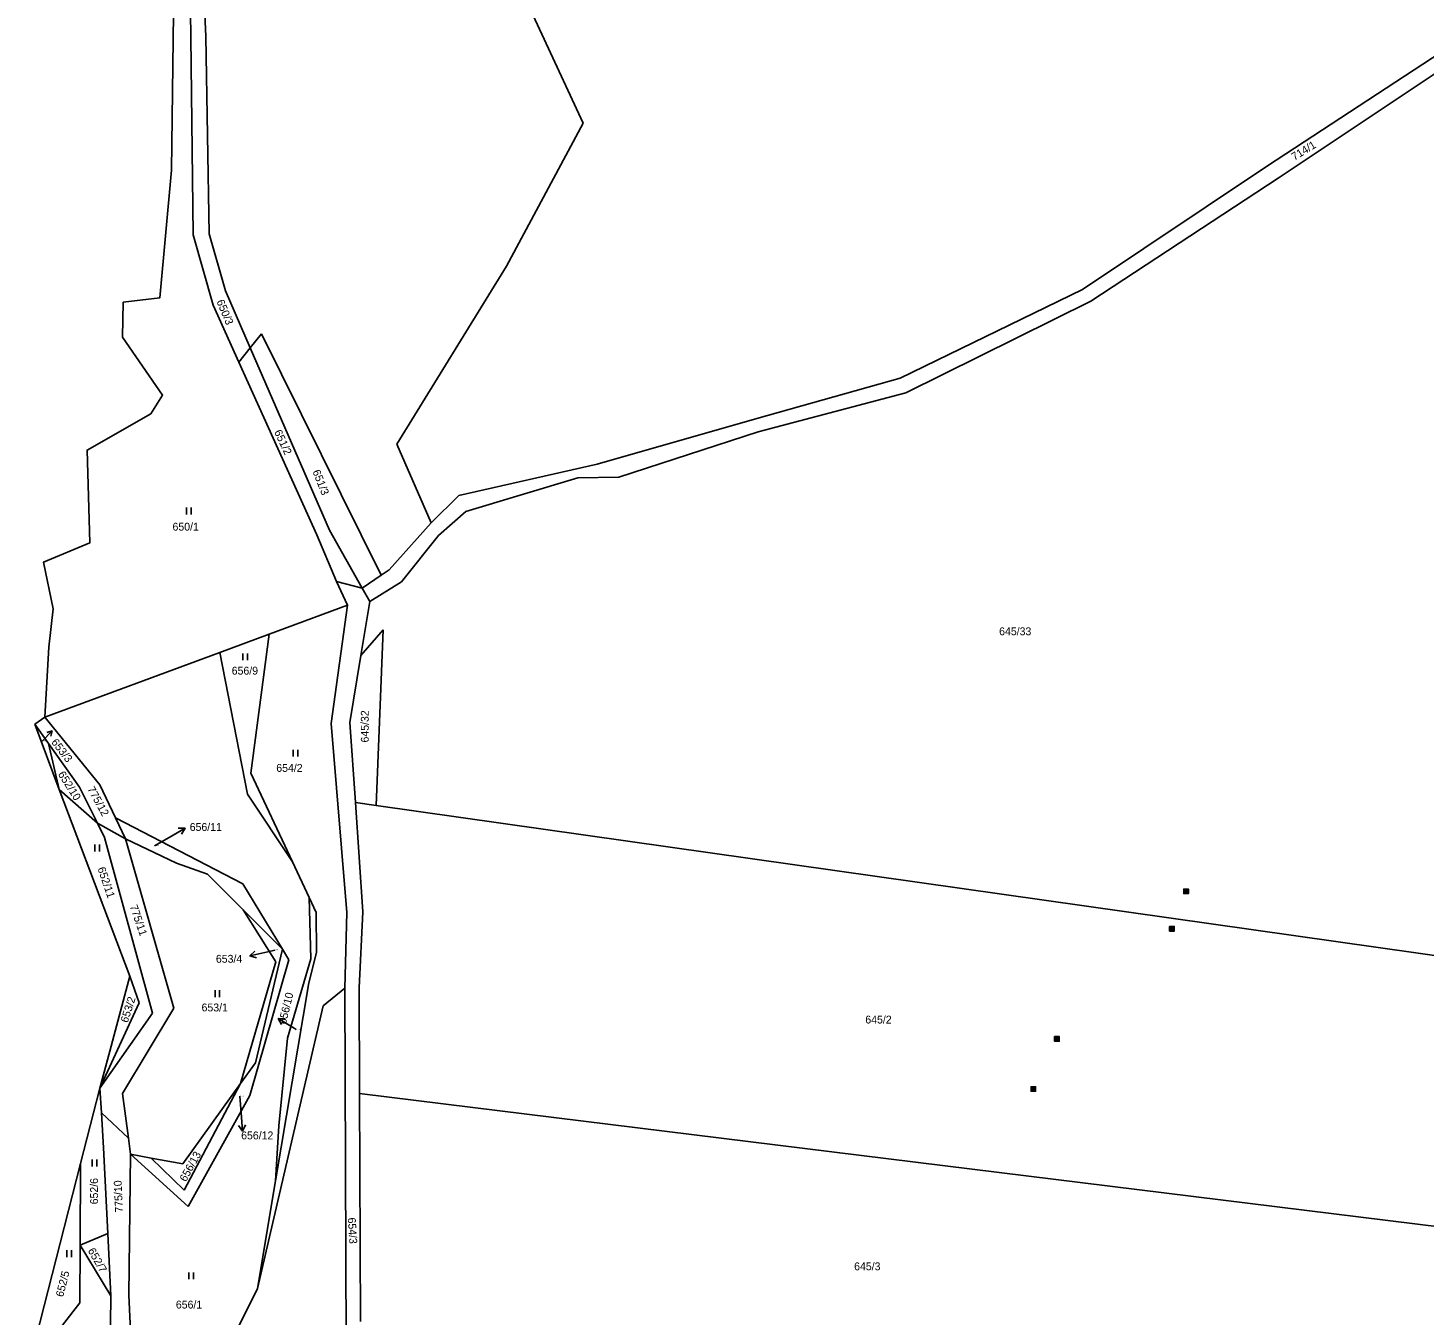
# Model space of a CAD drawing. Extents: x -694465 to -690527, y -983694 to -978978.
# Drawn here: x -692993.7 to -692691.9, y -982394.7 to -982116.3 of the extents above; entities that cross this region are included whole.
import ezdxf

# ---------------------------------------------------------------- set-up
doc = ezdxf.new("R2010")
doc.units = 0
for name, color, linetype in [('Vrstva 1', 7, 'Continuous'), ('Vrstva 16', 7, 'Continuous'), ('Vrstva 18', 7, 'Continuous'), ('Vrstva 25', 7, 'Continuous'), ('Vrstva 26', 7, 'Continuous'), ('Vrstva 29', 7, 'Continuous')]:
    doc.layers.add(name, color=color, linetype=linetype)

msp = doc.modelspace()

# ---------------------------------------------------------------- linework, layer by layer
at = {"layer": 'Vrstva 1'}
for points in [[(-692900.46, -982079.11), (-692873.66, -982136.89)], [(-692990.05, -982265.36), (-692989.18, -982250.19), (-692988.22, -982241.9), (-692990.3, -982231.83), (-692980.33, -982227.67), (-692980.9, -982207.61), (-692967.11, -982199.74), (-692964.58, -982195.7), (-692973.27, -982183.15), (-692973.07, -982175.61), (-692965.19, -982174.68), (-692962.67, -982147.1), (-692962.22, -982113.22), (-692967.43, -982104.67), (-692958.67, -982102.08)], [(-692958.67, -982102.08), (-692958.45, -982118.32)], [(-692955.26, -982118.17), (-692955.94, -982102.19)], [(-692958.45, -982118.32), (-692958, -982161.04)], [(-692954.48, -982160.87), (-692955.26, -982118.17)], [(-692688.24, -982121.53), (-692725.77, -982146.1)], [(-692723.48, -982148.79), (-692686.51, -982124.13)], [(-692873.66, -982136.89), (-692890.27, -982167.86)], [(-692725.77, -982146.1), (-692765.79, -982172.84)], [(-692763.99, -982175.39), (-692723.48, -982148.79)], [(-692958, -982161.04), (-692953.66, -982176.28)], [(-692951.01, -982173.19), (-692954.48, -982160.87)], [(-692890.27, -982167.86), (-692913.96, -982206.31)], [(-692945.66, -982185.49), (-692951.01, -982173.19)], [(-692765.79, -982172.84), (-692805.14, -982192.02)], [(-692953.66, -982176.28), (-692948.12, -982188.57)], [(-692803.94, -982195.24), (-692763.99, -982175.39)], [(-692943.22, -982182.44), (-692945.66, -982185.49)], [(-692917.32, -982234.68), (-692943.22, -982182.44)], [(-692945.66, -982185.49), (-692948.12, -982188.57)], [(-692928.51, -982224.94), (-692945.66, -982185.49)], [(-692948.12, -982188.57), (-692931.27, -982225.95)], [(-692805.14, -982192.02), (-692836.17, -982200.8)], [(-692835.88, -982203.66), (-692803.94, -982195.24)], [(-692836.17, -982200.8), (-692870.68, -982210.62)], [(-692865.99, -982213.44), (-692835.88, -982203.66)], [(-692913.96, -982206.31), (-692906.5, -982223.31)], [(-692870.68, -982210.62), (-692900.54, -982217.43)], [(-692899.01, -982220.87), (-692874.86, -982213.63)], [(-692874.86, -982213.63), (-692865.99, -982213.44)], [(-692900.54, -982217.43), (-692906.5, -982223.31)], [(-692904.93, -982226.04), (-692899.01, -982220.87)], [(-692921.43, -982237.48), (-692928.51, -982224.94)], [(-692906.5, -982223.31), (-692915.61, -982233.52)], [(-692931.27, -982225.95), (-692927.02, -982235.99)], [(-692912.93, -982236.11), (-692904.93, -982226.04)], [(-692915.61, -982233.52), (-692917.32, -982234.68)], [(-692927.02, -982235.99), (-692924.61, -982241.16)], [(-692927.02, -982235.99), (-692921.43, -982237.48)], [(-692917.32, -982234.68), (-692921.43, -982237.48)], [(-692919.77, -982240.36), (-692912.93, -982236.11)], [(-692921.43, -982237.48), (-692919.77, -982240.36)], [(-692924.61, -982241.16), (-692941.52, -982247.41)], [(-692924.61, -982241.16), (-692928.11, -982266.7)], [(-692921.71, -982252.02), (-692919.77, -982240.36)], [(-692941.52, -982247.41), (-692952.2, -982251.36)], [(-692945.52, -982277.46), (-692941.52, -982247.41)], [(-692916.87, -982246.44), (-692921.71, -982252.02)], [(-692918.39, -982284.48), (-692916.87, -982246.44)], [(-692952.2, -982251.36), (-692990.05, -982265.36)], [(-692952.2, -982251.36), (-692946.22, -982282.03)], [(-692924.11, -982266.51), (-692921.71, -982252.02)], [(-692992.22, -982266.9), (-692990.05, -982265.36)], [(-692992.22, -982266.9), (-692989.26, -982271.06)], [(-692986.91, -982280.97), (-692992.22, -982266.9)], [(-692978.14, -982279.99), (-692990.05, -982265.36)], [(-692928.11, -982266.7), (-692924.78, -982307.6)], [(-692922.91, -982283.84), (-692924.11, -982266.51)], [(-692989.26, -982271.06), (-692982.52, -982280.52)], [(-692986.91, -982280.97), (-692989.26, -982271.06)], [(-692936.5, -982296.64), (-692945.52, -982277.46)], [(-692978.64, -982288.31), (-692986.91, -982280.97)], [(-692971.67, -982321.38), (-692986.91, -982280.97)], [(-692982.52, -982280.52), (-692978.64, -982288.31)], [(-692974.77, -982287.11), (-692978.14, -982279.99)], [(-692946.22, -982282.03), (-692936.5, -982296.64)], [(-692921.27, -982307.43), (-692922.91, -982283.84)], [(-692922.91, -982283.84), (-692918.39, -982284.48)], [(-692918.39, -982284.48), (-692665.77, -982320.26)], [(-692978.64, -982288.31), (-692977.11, -982291.39)], [(-692972.62, -982291.65), (-692978.64, -982288.31)], [(-692947.24, -982301.38), (-692974.77, -982287.11)], [(-692972.62, -982291.65), (-692974.77, -982287.11)], [(-692977.11, -982291.39), (-692966.72, -982329.39)], [(-692962.13, -982328.29), (-692972.62, -982291.65)], [(-692972.62, -982291.65), (-692961.56, -982296.96)], [(-692961.56, -982296.96), (-692954.88, -982299.28)], [(-692936.5, -982296.64), (-692932.87, -982304.36)], [(-692954.88, -982299.28), (-692947.16, -982307.02)], [(-692938.65, -982315.55), (-692947.24, -982301.38)], [(-692932.87, -982304.36), (-692932.51, -982317.64)], [(-692931.35, -982307.6), (-692932.87, -982304.36)], [(-692947.16, -982307.02), (-692940.07, -982318.24)], [(-692938.65, -982315.55), (-692947.16, -982307.02)], [(-692931.33, -982316.24), (-692931.35, -982307.6)], [(-692924.78, -982307.6), (-692925.2, -982323.95)], [(-692922.08, -982323.88), (-692921.27, -982307.43)], [(-692944.52, -982340.09), (-692938.65, -982315.55)], [(-692937.28, -982317.8), (-692938.65, -982315.55)], [(-692940.07, -982318.24), (-692947.71, -982344.54)], [(-692945.69, -982347.16), (-692937.28, -982317.8)], [(-692932.51, -982317.64), (-692937.57, -982334.74)], [(-692932.94, -982322.8), (-692931.33, -982316.24)], [(-692978.11, -982345.55), (-692976.01, -982337.6), (-692971.67, -982321.38)], [(-692969.65, -982327.1), (-692971.67, -982321.38)], [(-692940.17, -982365.65), (-692932.94, -982322.8)], [(-692925.2, -982323.95), (-692929.9, -982327.78)], [(-692925.2, -982323.95), (-692924.62, -982477.68)], [(-692921.99, -982346.74), (-692922.08, -982323.88)], [(-692978.11, -982345.55), (-692969.65, -982327.1)], [(-692929.9, -982327.78), (-692944.09, -982388.89)], [(-692966.72, -982329.39), (-692978.11, -982345.55)], [(-692973.25, -982346.75), (-692962.13, -982328.29)], [(-692937.57, -982334.74), (-692939.43, -982353.76)], [(-692947.71, -982344.54), (-692944.52, -982340.09)], [(-692982.29, -982361.84), (-692978.11, -982345.55)], [(-692978.11, -982345.55), (-692977.79, -982350.91)], [(-692947.71, -982344.54), (-692960.19, -982361.97)], [(-692959.89, -982367.62), (-692947.71, -982344.54)], [(-692971.97, -982356.39), (-692973.25, -982346.75)], [(-692959.05, -982371.14), (-692945.69, -982347.16)], [(-692681.7, -982376.41), (-692921.99, -982346.74)], [(-692921.8, -982396.05), (-692921.99, -982346.74)], [(-692977.79, -982350.91), (-692977.33, -982358.48)], [(-692971.97, -982356.39), (-692977.79, -982350.91)], [(-692939.43, -982353.76), (-692940.17, -982365.65)], [(-692971.5, -982359.88), (-692971.97, -982356.39)], [(-692977.33, -982358.48), (-692976.44, -982377)], [(-692971.88, -982390.31), (-692971.5, -982359.88)], [(-692971.5, -982359.88), (-692959.05, -982371.14)], [(-692967.06, -982360.7), (-692971.5, -982359.88)], [(-692960.19, -982361.97), (-692967.06, -982360.7)], [(-692967.06, -982360.7), (-692959.89, -982367.62)], [(-692993.68, -982406.49), (-692982.29, -982361.84)], [(-692982.29, -982361.84), (-692982.4, -982379.54)], [(-692940.17, -982365.65), (-692944.09, -982388.89)], [(-692976.44, -982377), (-692982.4, -982379.54)], [(-692976.44, -982377), (-692975.79, -982390.5)], [(-692982.47, -982391.98), (-692982.4, -982379.54)], [(-692982.4, -982379.54), (-692975.79, -982390.5)], [(-692975.79, -982390.5), (-692975.92, -982402.83)], [(-692971.29, -982402.61), (-692971.88, -982390.31)], [(-692944.09, -982388.89), (-692962.48, -982426.03)], [(-692993.68, -982406.49), (-692982.47, -982391.98)]]:
    msp.add_lwpolyline(points, dxfattribs=at)
at = {"layer": 'Vrstva 16'}
for p, q in [((-692966.34, -982293.2), (-692963.18, -982291.38)), ((-692940.35, -982315.74), (-692941.81, -982316.08)), ((-692935.7, -982332.9), (-692936.16, -982332.62)), ((-692947.88, -982347.33), (-692947.6, -982350.89))]:
    msp.add_line(p, q, dxfattribs=at)
at = {"layer": 'Vrstva 25'}
for points in [[(-692959.38, -982220.03), (-692959.38, -982221.53)], [(-692958.38, -982221.53), (-692958.38, -982220.03)], [(-692947.2, -982251.56), (-692947.2, -982253.06)], [(-692946.2, -982253.06), (-692946.2, -982251.56)], [(-692936.37, -982272.39), (-692936.37, -982273.89)], [(-692935.37, -982273.89), (-692935.37, -982272.39)], [(-692979.21, -982292.91), (-692979.21, -982294.41)], [(-692978.21, -982294.41), (-692978.21, -982292.91)], [(-692953.24, -982324.38), (-692953.24, -982325.88)], [(-692952.24, -982325.88), (-692952.24, -982324.38)], [(-692979.76, -982361), (-692979.76, -982362.5)], [(-692978.76, -982362.5), (-692978.76, -982361)], [(-692985.28, -982380.6), (-692985.28, -982382.1)], [(-692984.28, -982382.1), (-692984.28, -982380.6)], [(-692958.92, -982385.41), (-692958.92, -982386.91)], [(-692957.92, -982386.91), (-692957.92, -982385.41)]]:
    msp.add_lwpolyline(points, dxfattribs=at)
at = {"layer": 'Vrstva 26'}
for points in [[(-692743.87, -982302.519), (-692742.871, -982302.519), (-692742.871, -982303.52), (-692743.87, -982303.52), (-692743.87, -982302.521), (-692743.81, -982302.58), (-692742.93, -982302.58), (-692742.93, -982302.66), (-692743.81, -982302.66), (-692743.81, -982302.74), (-692742.93, -982302.74), (-692742.93, -982302.82), (-692743.81, -982302.82), (-692743.81, -982302.9), (-692742.93, -982302.9), (-692742.93, -982302.98), (-692743.81, -982302.98), (-692743.81, -982303.06), (-692742.93, -982303.06), (-692742.93, -982303.14), (-692743.81, -982303.14), (-692743.81, -982303.22), (-692742.93, -982303.22), (-692742.93, -982303.3), (-692743.81, -982303.3), (-692743.81, -982303.38), (-692742.93, -982303.38), (-692742.93, -982303.46), (-692743.81, -982303.46)], [(-692746.92, -982310.599), (-692745.921, -982310.599), (-692745.921, -982311.6), (-692746.92, -982311.6), (-692746.92, -982310.601), (-692746.86, -982310.66), (-692745.98, -982310.66), (-692745.98, -982310.74), (-692746.86, -982310.74), (-692746.86, -982310.82), (-692745.98, -982310.82), (-692745.98, -982310.9), (-692746.86, -982310.9), (-692746.86, -982310.98), (-692745.98, -982310.98), (-692745.98, -982311.06), (-692746.86, -982311.06), (-692746.86, -982311.14), (-692745.98, -982311.14), (-692745.98, -982311.22), (-692746.86, -982311.22), (-692746.86, -982311.3), (-692745.98, -982311.3), (-692745.98, -982311.38), (-692746.86, -982311.38), (-692746.86, -982311.46), (-692745.98, -982311.46), (-692745.98, -982311.54), (-692746.86, -982311.54)], [(-692771.79, -982334.439), (-692770.791, -982334.439), (-692770.791, -982335.44), (-692771.79, -982335.44), (-692771.79, -982334.441), (-692771.73, -982334.5), (-692770.85, -982334.5), (-692770.85, -982334.58), (-692771.73, -982334.58), (-692771.73, -982334.66), (-692770.85, -982334.66), (-692770.85, -982334.74), (-692771.73, -982334.74), (-692771.73, -982334.82), (-692770.85, -982334.82), (-692770.85, -982334.9), (-692771.73, -982334.9), (-692771.73, -982334.98), (-692770.85, -982334.98), (-692770.85, -982335.06), (-692771.73, -982335.06), (-692771.73, -982335.14), (-692770.85, -982335.14), (-692770.85, -982335.22), (-692771.73, -982335.22), (-692771.73, -982335.3), (-692770.85, -982335.3), (-692770.85, -982335.38), (-692771.73, -982335.38)], [(-692776.88, -982345.259), (-692775.881, -982345.259), (-692775.881, -982346.26), (-692776.88, -982346.26), (-692776.88, -982345.261), (-692776.82, -982345.32), (-692775.94, -982345.32), (-692775.94, -982345.4), (-692776.82, -982345.4), (-692776.82, -982345.48), (-692775.94, -982345.48), (-692775.94, -982345.56), (-692776.82, -982345.56), (-692776.82, -982345.64), (-692775.94, -982345.64), (-692775.94, -982345.72), (-692776.82, -982345.72), (-692776.82, -982345.8), (-692775.94, -982345.8), (-692775.94, -982345.88), (-692776.82, -982345.88), (-692776.82, -982345.96), (-692775.94, -982345.96), (-692775.94, -982346.04), (-692776.82, -982346.04), (-692776.82, -982346.12), (-692775.94, -982346.12), (-692775.94, -982346.2), (-692776.82, -982346.2)]]:
    msp.add_lwpolyline(points, dxfattribs=at)
at = {"layer": 'Vrstva 29'}
for points in [[(-692990.57, -982270.55), (-692988.452, -982268.314), (-692989.56, -982268.643)], [(-692988.721, -982269.438), (-692988.452, -982268.314)], [(-692963.18, -982291.38), (-692959.714, -982289.383), (-692961.215, -982289.382)], [(-692960.466, -982290.682), (-692959.714, -982289.383)], [(-692944.61, -982315.963), (-692945.705, -982316.989)], [(-692941.81, -982316.08), (-692945.705, -982316.989), (-692944.269, -982317.424)], [(-692936.16, -982332.62), (-692939.571, -982330.53), (-692938.854, -982331.849)], [(-692938.07, -982330.57), (-692939.571, -982330.53)], [(-692947.6, -982350.89), (-692947.283, -982354.877), (-692946.638, -982353.522)], [(-692948.133, -982353.641), (-692947.283, -982354.877)]]:
    msp.add_lwpolyline(points, dxfattribs=at)

# ---------------------------------------------------------------- texts
at = {"layer": 'Vrstva 16'}
for s, rotation, p in [('653/3', 307.79293, (-692988.741, -982270.812)), ('656/10', 76.48987, (-692937.913, -982331.882))]:
    msp.add_text(s, height=1.7, rotation=rotation, dxfattribs=at).set_placement(p)
for s, p in [('656/11', (-692958.713, -982289.95)), ('653/4', (-692953.053, -982318.46)), ('656/12', (-692947.593, -982356.65))]:
    msp.add_text(s, height=1.7, dxfattribs=at).set_placement(p)
at = {"layer": 'Vrstva 18'}
for s, rotation, p in [('714/1', 31.51268, (-692719.959, -982145.05)), ('650/3', 292.49496, (-692952.955, -982175.45)), ('651/2', 294.95867, (-692940.509, -982203.664)), ('651/3', 291.63552, (-692932.208, -982212.232)), ('645/32', 90.01167, (-692920.02, -982270.823)), ('652/10', 302.46442, (-692987.268, -982277.701)), ('775/12', 298.79749, (-692980.896, -982280.888)), ('652/11', 288.88532, (-692978.664, -982298.068)), ('775/11', 288.88532, (-692971.693, -982306.245)), ('653/2', 72.02079, (-692972.13, -982331.55)), ('656/13', 61.19189, (-692959.528, -982365.957)), ('652/6', 90.01167, (-692978.53, -982370.703)), ('775/10', 92.70457, (-692973.121, -982372.433)), ('654/3', 273.58735, (-692924.543, -982373.61)), ('652/7', 299.71422, (-692980.793, -982380.71)), ('652/5', 75.57313, (-692986.071, -982390.844))]:
    msp.add_text(s, height=1.7, rotation=rotation, dxfattribs=at).set_placement(p)
for s, height, p in [('650/1', 1.7, (-692962.429, -982225.01)), ('645/33', 1.7, (-692783.773, -982247.64)), ('656/9', 1.7, (-692949.633, -982256.15)), ('653/3', 0.2, (-692990.528, -982270.55)), ('654/2', 1.7, (-692940.004, -982277.18)), ('656/11', 0.2, (-692966.298, -982293.2)), ('653/4', 0.2, (-692940.308, -982315.74)), ('653/1', 1.7, (-692956.149, -982328.98)), ('645/2', 1.7, (-692812.693, -982331.6)), ('656/10', 0.2, (-692935.658, -982332.9)), ('656/12', 0.2, (-692947.838, -982347.33)), ('645/3', 1.7, (-692815.113, -982384.96)), ('656/1', 1.7, (-692961.702, -982393.23))]:
    msp.add_text(s, height=height, dxfattribs=at).set_placement(p)

doc.saveas('drawing.dxf')
